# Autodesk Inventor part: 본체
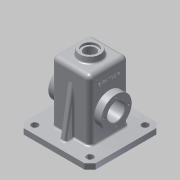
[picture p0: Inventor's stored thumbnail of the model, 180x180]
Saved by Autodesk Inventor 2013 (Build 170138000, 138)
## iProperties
Created: 2016-02
Part Number: 본체
Material: 알루미늄 6061
Document SubType Name: Modeling
Designer: dgall
Density: 2.71054 g/cm^3
Mass: 933 g
Surface Area: 1043.48 cm^2
Volume: 344.212 cm^3
Author: dgall
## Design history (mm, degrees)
sketch "스케치1"
  geometry: L1 (-35, 35)-(35, 35); L2 (35, 35)-(35, -35); L3 (35, -35)-(-35, -35); L4 (-35, -35)-(-35, 35); 1 further point
  constraints: 8 end point, 2 parallel, 1 horizontal, 1 perpendicular
  dimensions: "d0" = 70 distance between parallel lines of L2 L4; "d2" = 70 distance between parallel lines of L3 L1; "d3" = 35 distance from line of point (0, 0) L1; "d4" = 35 distance from line of L4 point (0, 0)
extrude "돌출1" new body sketch "스케치1" stored distance "d5" = 120; taper "d6" = 0 deg
feature "쉘1" dims "d7" = 5
sketch "스케치2"
  geometry: L1 (35, 35)-(-35, 35) reference; L2 (-35, 35)-(-35, -35) reference; L3 (-35, -35)-(35, -35) reference; L4 (35, -35)-(35, 35) reference; L5 (-65, 65)-(65, 65); L6 (65, 65)-(65, -65); L7 (65, -65)-(-65, -65); L8 (-65, -65)-(-65, 65); 1 further point
  constraints: 8 end point, 2 parallel, 1 horizontal, 1 perpendicular
  dimensions: "d8" = 130 distance of L5.end L6.end; "d10" = 130 distance of L5.start L5.end; "d11" = 65 distance from line of point (0, 0) L5 (= 0.5 x d8); "d12" = 65 distance from line of point (0, 0) L8 (= 0.5 x d10)
extrude "돌출2" join sketch "스케치2" distance "d13" = 10; taper "d14" = 0 deg
chamfer "모따기1" distance "d15" = 10; stored, may be unused: second distance "d16" = 2, angle "d17" = 45 deg
node "작업 평면1"
sketch "스케치3"
  geometry: L1 (-55, -60)-(55, -60) reference; C1 r 27.5 at (0, -5); 1 further point
  constraints: 1 centre point
  dimensions: "d19" = 55 distance from line of L1 C1.centre; "d20" = 0 horizontal distance of point (0, 0) C1.centre; "d21" = 55 diameter of C1
extrude "돌출3" join sketch "스케치3" stored distance "d22" = 10; taper "d23" = 0 deg
sketch "스케치4"
  geometry: L1 (-30, 55)-(-30, -60) reference; L2 (-30, 22.5)-(-23, 15.5); L3 (-23, 15.5)-(-23, 11); L4 (-23, 11)-(-30, 11); L5 (-48, -32.5)-(-48, 22.5) reference; L6 (-48, -5)-(88.253, -5); L7 (-30, 22.5)-(-30, 11); 1 further point
  constraints: 10 end point, 2 perpendicular, 2 point on line, 1 collinear, 1 midpoint, 1 parallel
  dimensions: "d24" = 32 diameter of L4 L6; "d26" = 55 diameter of L2.start L6; "d27" = 7 distance between parallel lines of L1 L3; "d28" = 135 deg angle of L1 L2
revolve "회전1" sketch "스케치4" stored, may be unused: angle "d29" = 90 deg
sketch "스케치5"
  geometry: C1 r 27.5 at (0, 0) reference; C2 r 16 at (0, 0); 1 further point
  constraints: 1 centre point, 1 coincident
  dimensions: "d30" = 32 diameter of C2
extrude "돌출4" cut sketch "스케치5" stored distance "d32" = 10; taper "d33" = 0 deg
sketch "스케치7"
  geometry: C1 r 20 at (0, 0); 1 further point
  constraints: 1 centre point, 1 coincident
  dimensions: "d34" = 40 diameter of C1
extrude "돌출5" join sketch "스케치7" distance "d36" = 10; taper "d37" = -10 deg
sketch "스케치8"
  geometry: C1 r 18.237 at (0, 0) reference; C2 r 14 at (0, 0)
  constraints: 1 centre point, 1 coincident
  dimensions: "d38" = 28 diameter of C2
extrude "돌출6" cut sketch "스케치8" distance "d40" = 4; taper "d41" = 0 deg
sketch "스케치9"
  geometry: C1 r 14 at (0, 0) reference; C2 r 10.5 at (0, 0)
  constraints: 1 centre point, 1 coincident
  dimensions: "d42" = 21 diameter of C2
extrude "돌출7" cut sketch "스케치9" stored distance "d44" = 4; taper "d45" = 0 deg
fillet "모깎기1" dims "d46" = 3
fillet "모깎기2" dims "d47" = 3
fillet "모깎기3" dims "d48" = 8
fillet "모깎기4" dims "d49" = 8
chamfer "모따기2" distance "d50" = 1; stored, may be unused: second distance "d51" = 2, angle "d52" = 45 deg
fillet "모깎기5" dims "d53" = 0.5
fillet "모깎기6" dims "d54" = 0.5
sketch "스케치10"
  geometry: L1 (35, -50)-(35, 52) reference; L2 (-55, -50)-(55, -50) reference; L3 (65, -50)-(55, -50) reference; L4 (35, 35.069)-(50, -50); L5 (65, -60)-(65, -50) reference; L6 (35, 35.069)-(35, -50); L7 (35, -50)-(50, -50); 1 further point
  constraints: 6 end point, 2 collinear, 2 point on line
  dimensions: "d55" = 15 distance from line of L5 L4.end; "d57" = 10 deg angle of L4 L5
fillet "모깎기7" dims "d58" = 3
sketch "스케치11"
  geometry: L1 (55, 65)-(-55, 65) reference; L2 (-65, 55)-(-65, -55) reference; C1 r 6 at (-50, 50); 1 further point
  constraints: 1 centre point
  dimensions: "d59" = 15 distance from line of C1.centre L2; "d60" = 15 distance from line of C1.centre L1; "d61" = 12 diameter of C1
extrude "돌출8" cut sketch "스케치11" stored distance "d62" = 4; taper "d63" = 0 deg
fillet "모깎기8" dims "d70" = 0.5
extrude "돌출9" join sketch "스케치10" stored distance "d71" = 10; taper "d72" = 0 deg
fillet "모깎기9" dims "d73" = 3
fillet "모깎기10" dims "d74" = 3
fillet "모깎기11" dims "d75" = 3
fillet "모깎기12" dims "d76" = 3
fillet "모깎기13" dims "d77" = 3
sketch "스케치12"
  geometry: C1 r 17 at (0, 0) reference; A1 r 22.5 centre (0, 0) between (0, 22.5) and (22.5, 0); 3 further points
  constraints: 4 point on circle, 1 centre point, 1 coincident
  dimensions: "d78" = 45 diameter of A1
hole "구멍1" sketch "스케치12" at (0, 22.5), (22.5, 0), (0, -22.5), (-22.5, 0) diameter "d80" = 3.242; stored, may be unused: countersink angle "d84" = 90 deg, drill point angle "d86" = 118 deg; dims "d81" = 8, "d82" = 4, "d83" = 2, "d85" = 10
sketch "스케치13"
  geometry: L1 (6.261, -8.998)-(47.739, -8.998); L2 (47.739, -8.998)-(47.739, -15.002); L3 (47.739, -15.002)-(6.261, -15.002); L4 (6.261, -15.002)-(6.261, -8.998); L5 (6.261, -12)-(47.739, -12); L6 (27, -8.998)-(27, -15.002); L7 (62, -99)-(62, 0) reference; L8 (8.763, 18)-(45.237, 18) reference; 1 further point
  constraints: 4 end point, 4 midpoint, 2 other
  dimensions: "d87" = 35 distance between parallel lines of L7 L6; "d88" = 30 distance between parallel lines of L8 L5
extrude "돌출10" join sketch "스케치13" distance "d89" = 0.5; taper "d90" = 0 deg
node "솔리드1"
mirror "대칭1"
mirror "대칭2"
pattern_linear "직사각형 패턴1" dims "d66" = 100
mirror "대칭3"
mirror "대칭4"
node "작업 평면2"
other parameters: "d18" = -48
